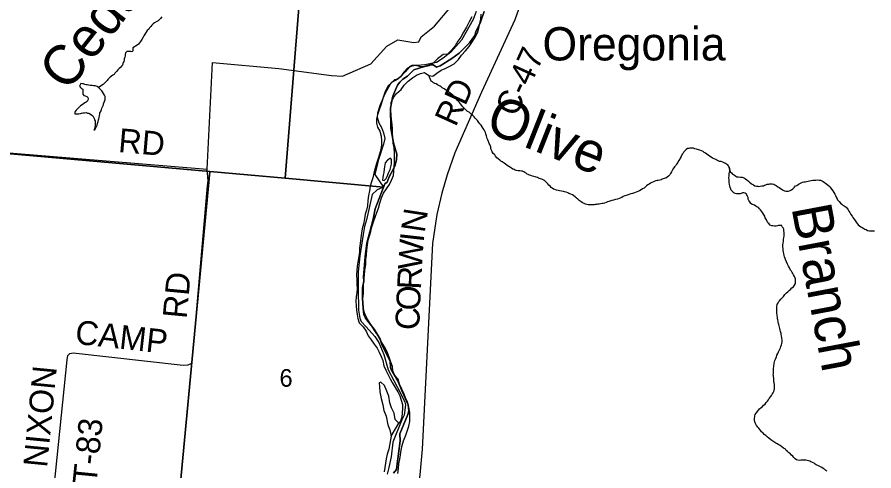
# Model space of a CAD drawing. Extents: x 1310247 to 1664935, y 284496 to 704931.
# Drawn here: x 1511194 to 1521928, y 525811 to 531499 of the extents above; entities that cross this region are included whole.
import ezdxf

# ---------------------------------------------------------------- set-up
doc = ezdxf.new("R2010")
doc.units = 0
for name, color, linetype in [('GM_X_Adjacent_County', 7, 'Continuous'), ('GM_X_City_Street', 7, 'Continuous'), ('GM_X_County', 7, 'Continuous'), ('GM_X_County_Road_Text', 7, 'Continuous'), ('GM_X_County_Subdivision_Text', 7, 'Continuous'), ('GM_X_Interstate_Route', 7, 'Continuous'), ('GM_X_Minor_Lake_Text', 7, 'Continuous'), ('GM_X_Minor_River', 7, 'Continuous'), ('GM_X_Minor_River_Text', 7, 'Continuous'), ('GM_X_Township_Road', 7, 'Continuous'), ('GM_X_Township_Subdivision', 7, 'Continuous'), ('GM_X_US_Location', 7, 'Continuous')]:
    doc.layers.add(name, color=color, linetype=linetype)

msp = doc.modelspace()

# ---------------------------------------------------------------- linework, layer by layer
at = {"layer": 'GM_X_Adjacent_County'}
for points in [[(1517045, 531569), (1517000, 531435), (1516943, 531315), (1516930, 531269), (1516862, 531178), (1516734, 531049), (1516639, 530979), (1516492, 530888), (1516449, 530870), (1516408, 530900), (1516365, 530901), (1516165, 530839), (1516086, 530759), (1516026, 530720), (1515989, 530685), (1515959, 530648), (1515909, 530527), (1515896, 530491), (1515873, 530356), (1515878, 530109), (1515911, 529925), (1515950, 529780), (1515948, 529716), (1515930, 529643), (1515910, 529596), (1515855, 529498), (1515829, 529432), (1515800, 529411), (1515679, 529094), (1515654, 528965), (1515574, 528667), (1515556, 528493), (1515532, 528243), (1515539, 528189), (1515523, 528105), (1515520, 527971), (1515534, 527805), (1515539, 527773), (1515560, 527727), (1515668, 527586), (1515742, 527463), (1515768, 527384), (1515866, 527186), (1515871, 527109), (1515881, 527082), (1515963, 526940), (1516019, 526807), (1516095, 526641), (1516103, 526562), (1516090, 526517), (1515989, 526277), (1515992, 526188), (1515953, 525866), (1515946, 525829), (1515910, 525782)], [(1515910, 525782), (1515946, 525829), (1515953, 525866), (1515992, 526188), (1515989, 526277), (1516090, 526517), (1516103, 526562), (1516095, 526641), (1516019, 526807), (1515963, 526940), (1515881, 527082), (1515871, 527109), (1515866, 527186), (1515768, 527384), (1515742, 527463), (1515668, 527586), (1515560, 527727), (1515539, 527773), (1515534, 527805), (1515520, 527971), (1515523, 528105), (1515539, 528189), (1515532, 528243), (1515556, 528493), (1515574, 528667), (1515654, 528965), (1515679, 529094), (1515800, 529411), (1515829, 529432), (1515855, 529498), (1515910, 529596), (1515930, 529643), (1515948, 529716), (1515950, 529780), (1515911, 529925), (1515878, 530109), (1515873, 530356), (1515896, 530491), (1515909, 530527), (1515959, 530648), (1515989, 530685), (1516026, 530720), (1516086, 530759), (1516165, 530839), (1516365, 530901), (1516408, 530900), (1516449, 530870), (1516492, 530888), (1516639, 530979), (1516734, 531049), (1516862, 531178), (1516930, 531269), (1516943, 531315), (1517000, 531435), (1517045, 531569)]]:
    msp.add_lwpolyline(points, dxfattribs=at)
at = {"layer": 'GM_X_City_Street'}
msp.add_line((1515881, 526248), (1515978, 526408), dxfattribs=at)
for points in [[(1515538, 528202), (1515547, 528266), (1515552, 528326), (1515561, 528398), (1515564, 528462), (1515569, 528516), (1515574, 528580), (1515583, 528646), (1515594, 528704), (1515609, 528756), (1515624, 528810), (1515639, 528869), (1515660, 528931), (1515681, 528991), (1515702, 529051), (1515721, 529105), (1515740, 529168), (1515759, 529232), (1515784, 529292), (1515820, 529345), (1515859, 529399), (1515884, 529457), (1515909, 529512), (1515914, 529566), (1515919, 529622), (1515922, 529682), (1515921, 529738), (1515922, 529792), (1515917, 529863), (1515907, 529921), (1515900, 529985), (1515897, 530049), (1515896, 530103), (1515891, 530155), (1515884, 530218), (1515881, 530268), (1515876, 530332), (1515881, 530430), (1515908, 530490), (1515949, 530543), (1516004, 530590), (1516045, 530644), (1516094, 530697), (1516147, 530740), (1516197, 530772), (1516248, 530791), (1516298, 530804), (1516351, 530767), (1516403, 530760), (1516454, 530796), (1516507, 530833), (1516557, 530856), (1516616, 530883), (1516670, 530914), (1516723, 530966), (1516762, 531021), (1516811, 531078), (1516856, 531130), (1516899, 531195), (1516934, 531249), (1516961, 531300), (1516980, 531360), (1516993, 531422), (1517004, 531474), (1517009, 531536)], [(1516890, 531504), (1516859, 531438), (1516824, 531375), (1516787, 531309)], [(1516787, 531309), (1516752, 531248), (1516717, 531196), (1516680, 531141), (1516637, 531083), (1516586, 531036), (1516532, 531031), (1516495, 531001), (1516461, 530976), (1516406, 530921), (1516355, 530889), (1516301, 530876), (1516247, 530877), (1516193, 530892), (1516141, 530885), (1516086, 530859), (1516039, 530808), (1515998, 530749), (1515944, 530707), (1515893, 530684), (1515840, 530635), (1515805, 530565), (1515786, 530502), (1515769, 530450), (1515750, 530394), (1515731, 530336), (1515709, 530276), (1515696, 530225), (1515697, 530168), (1515710, 530118), (1515737, 530068), (1515756, 530007), (1515760, 529949), (1515761, 529897), (1515750, 529841), (1515735, 529783), (1515716, 529728), (1515697, 529666), (1515680, 529606), (1515663, 529542), (1515650, 529486), (1515633, 529434), (1515619, 529379), (1515610, 529323), (1515597, 529261), (1515588, 529199), (1515583, 529133), (1515570, 529081), (1515555, 529029), (1515544, 528971), (1515533, 528905), (1515518, 528845), (1515507, 528791), (1515500, 528731), (1515491, 528663), (1515484, 528601), (1515482, 528551), (1515475, 528497), (1515464, 528428), (1515453, 528376), (1515450, 528324), (1515447, 528268), (1515448, 528207), (1515449, 528151), (1515453, 528097), (1515450, 528047), (1515443, 527993), (1515438, 527939), (1515441, 527881), (1515446, 527827), (1515454, 527771), (1515461, 527720), (1515480, 527668), (1515531, 527617), (1515565, 527561), (1515594, 527504), (1515629, 527453), (1515668, 527401), (1515704, 527348), (1515731, 527298), (1515754, 527245), (1515775, 527193), (1515788, 527128), (1515812, 527072), (1515839, 527022), (1515868, 526967), (1515893, 526917), (1515931, 526858), (1515962, 526803), (1515987, 526751), (1516006, 526696), (1516021, 526644), (1516023, 526592), (1516018, 526540), (1516015, 526486), (1515998, 526434), (1515978, 526408)], [(1515870, 529729), (1515836, 529706), (1515803, 529671), (1515801, 529646), (1515794, 529596), (1515788, 529552), (1515781, 529518), (1515775, 529490), (1515770, 529456), (1515794, 529452), (1515818, 529478), (1515831, 529503)], [(1515831, 529503), (1515852, 529557), (1515868, 529589), (1515885, 529657), (1515886, 529713), (1515870, 529729)], [(1515962, 525778), (1515973, 525842), (1515978, 525898), (1515987, 525958), (1515998, 526014), (1516007, 526071), (1516020, 526131), (1516036, 526187), (1516062, 526259), (1516082, 526311), (1516101, 526370), (1516112, 526432), (1516115, 526488), (1516114, 526545), (1516103, 526609), (1516086, 526671), (1516061, 526728), (1516038, 526784), (1516014, 526837), (1515983, 526899), (1515968, 526959), (1515921, 527010), (1515900, 527065), (1515896, 527119), (1515877, 527173), (1515856, 527238), (1515835, 527292), (1515806, 527355), (1515769, 527413), (1515734, 527472), (1515702, 527528), (1515667, 527579), (1515632, 527634), (1515595, 527690), (1515567, 527741), (1515548, 527791), (1515529, 527856), (1515524, 527910), (1515525, 527966), (1515534, 528040), (1515535, 528092), (1515534, 528148), (1515538, 528202)], [(1515978, 526408), (1515932, 526457), (1515918, 526534), (1515885, 526602), (1515863, 526665), (1515849, 526749), (1515826, 526811), (1515797, 526882), (1515749, 526923), (1515731, 526913), (1515732, 526863), (1515739, 526803), (1515756, 526720), (1515775, 526640), (1515790, 526570), (1515817, 526495), (1515839, 526389), (1515864, 526326), (1515881, 526248)], [(1515881, 526248), (1515850, 526082), (1515829, 526020), (1515817, 525962), (1515810, 525908), (1515801, 525854), (1515792, 525798)]]:
    msp.add_lwpolyline(points, dxfattribs=at)
at = {"layer": 'GM_X_County'}
for points in [[(1509752, 536706), (1515094, 536260), (1514552, 529479), (1513608, 529562), (1509176, 529957)], [(1509176, 529957), (1513608, 529562), (1513069, 523850), (1507676, 524403), (1508208, 530054)]]:
    msp.add_lwpolyline(points, close=True, dxfattribs=at)
for points in [[(1516944, 531569), (1516906, 531470), (1516760, 531212), (1516629, 531061), (1516532, 530983), (1516447, 530932), (1516303, 530902), (1516207, 530894), (1516139, 530891), (1516116, 530882), (1516055, 530813), (1515998, 530752), (1515964, 530722), (1515920, 530715), (1515875, 530670), (1515801, 530539), (1515742, 530398), (1515708, 530297), (1515705, 530243), (1515726, 530173), (1515761, 530114), (1515786, 530050), (1515799, 529977), (1515786, 529908), (1515720, 529715), (1515709, 529665), (1515677, 529526), (1515782, 529366), (1514552, 529479), (1515094, 536260)], [(1513069, 523850), (1513608, 529562), (1514552, 529479), (1515782, 529366), (1515704, 529333), (1515641, 529274), (1515610, 529127), (1515573, 528960), (1515546, 528874), (1515528, 528775), (1515487, 528505), (1515468, 528308), (1515468, 528092), (1515470, 527826), (1515486, 527724), (1515503, 527685), (1515566, 527616), (1515674, 527496), (1515724, 527421), (1515788, 527272), (1515844, 527079), (1515914, 526944), (1516001, 526779), (1516053, 526672), (1516061, 526640), (1516045, 526508), (1516013, 526449), (1515901, 526171), (1515880, 525987), (1515849, 525852), (1515828, 525770)]]:
    msp.add_lwpolyline(points, dxfattribs=at)
at = {"layer": 'GM_X_County_Road_Text'}
msp.add_lwpolyline([(1517821, 531984), (1517731, 532060), (1517631, 532163), (1517557, 531889), (1517498, 531653), (1517430, 531466), (1517014, 530559), (1516676, 529797), (1516581, 529524), (1516514, 529294), (1516453, 529026), (1516398, 528660), (1516269, 526085), (1516241, 525763), (1516213, 525605), (1516112, 525362), (1515971, 525133), (1515662, 524760)], dxfattribs=at)
at = {"layer": 'GM_X_County_Subdivision_Text'}
for points in [[(1513575, 529592), (1513641, 530929), (1514474, 530857), (1515134, 530767), (1515270, 530757), (1515627, 530915), (1515826, 531133), (1515963, 531215), (1516163, 531181), (1516227, 531188), (1516254, 531250), (1516421, 531386), (1516627, 531628), (1516762, 531921), (1516806, 532231), (1516709, 532812), (1516715, 532994)], [(1508204, 530036), (1513575, 529592)], [(1513581, 529384), (1513586, 529448), (1513575, 529592)], [(1511247, 524193), (1511369, 525485), (1511390, 525537), (1511442, 525545), (1511595, 525529), (1511640, 525529), (1511659, 525612), (1511821, 527204), (1511830, 527256), (1511854, 527283), (1511897, 527290), (1513276, 527136), (1513336, 527141), (1513384, 527163), (1513389, 527215), (1513581, 529384)]]:
    msp.add_lwpolyline(points, dxfattribs=at)
at = {"layer": 'GM_X_Minor_River'}
for points in [[(1511993, 530668), (1511974, 530633), (1511988, 530618), (1512002, 530606), (1512016, 530594), (1512019, 530580), (1512017, 530559), (1512016, 530533), (1512030, 530515), (1512048, 530511), (1512066, 530502), (1512080, 530490), (1512085, 530474), (1512081, 530460), (1512073, 530442), (1512058, 530432), (1512044, 530424), (1512026, 530413), (1512007, 530401), (1511989, 530385), (1511968, 530367), (1511950, 530350), (1511933, 530334), (1511923, 530316), (1511916, 530302), (1511918, 530286), (1511932, 530286), (1511954, 530285), (1511968, 530287), (1511987, 530291), (1512001, 530295), (1512019, 530298), (1512039, 530300), (1512059, 530302), (1512077, 530297), (1512091, 530293), (1512111, 530284), (1512129, 530272), (1512143, 530260), (1512151, 530244), (1512158, 530227), (1512164, 530213), (1512170, 530199), (1512172, 530185), (1512171, 530171), (1512173, 530141), (1512168, 530123), (1512162, 530099), (1512155, 530083), (1512172, 530094), (1512180, 530110), (1512190, 530126), (1512195, 530144), (1512201, 530166), (1512208, 530192), (1512212, 530210), (1512217, 530226), (1512221, 530242), (1512224, 530266), (1512228, 530284), (1512230, 530298), (1512241, 530316), (1512250, 530342), (1512254, 530358), (1512262, 530376), (1512275, 530400), (1512277, 530414), (1512286, 530432), (1512292, 530452), (1512297, 530466), (1512297, 530480), (1512295, 530502), (1512288, 530522), (1512276, 530543), (1512264, 530561), (1512253, 530577), (1512213, 530618)], [(1512213, 530618), (1512198, 530628), (1512184, 530633), (1512170, 530637), (1512151, 530639), (1512135, 530640), (1512121, 530640), (1512107, 530640), (1512089, 530645), (1512073, 530649), (1512059, 530651), (1512043, 530655), (1512027, 530662), (1512011, 530664), (1511993, 530668)]]:
    msp.add_lwpolyline(points, dxfattribs=at)
at = {"layer": 'GM_X_Minor_River_Text'}
for points in [[(1513006, 531504), (1512990, 531482), (1512975, 531466), (1512959, 531454), (1512943, 531445), (1512914, 531427), (1512900, 531415), (1512883, 531397), (1512871, 531382), (1512852, 531366), (1512842, 531350), (1512825, 531330), (1512802, 531296), (1512788, 531279), (1512780, 531265), (1512771, 531247), (1512756, 531219), (1512738, 531195), (1512727, 531177), (1512715, 531161), (1512698, 531146), (1512678, 531134), (1512664, 531126), (1512645, 531115), (1512643, 531092), (1512644, 531078), (1512632, 531065), (1512618, 531067), (1512600, 531067), (1512586, 531067), (1512570, 531066), (1512553, 531050), (1512549, 531030), (1512546, 531012), (1512544, 530998), (1512536, 530978), (1512533, 530960), (1512529, 530944), (1512524, 530930), (1512520, 530916), (1512512, 530898), (1512501, 530884), (1512487, 530868), (1512472, 530854), (1512456, 530837), (1512441, 530823), (1512431, 530809), (1512417, 530795), (1512408, 530781), (1512392, 530772), (1512376, 530758), (1512361, 530746), (1512349, 530732), (1512332, 530718), (1512320, 530705), (1512304, 530689), (1512287, 530673), (1512271, 530655), (1512213, 530618)], [(1516857, 530306), (1516837, 530318), (1516821, 530331), (1516807, 530347), (1516793, 530357), (1516778, 530376), (1516766, 530390), (1516748, 530412), (1516735, 530429), (1516721, 530445), (1516707, 530459), (1516690, 530482), (1516680, 530496), (1516666, 530504), (1516652, 530521), (1516636, 530535), (1516621, 530547), (1516603, 530560), (1516587, 530570), (1516573, 530578), (1516559, 530589), (1516543, 530599), (1516521, 530614), (1516507, 530624), (1516494, 530632), (1516478, 530642), (1516460, 530651), (1516442, 530661), (1516428, 530669), (1516412, 530676), (1516396, 530688), (1516382, 530698), (1516351, 530767)], [(1518331, 529150), (1518317, 529154), (1518297, 529162), (1518277, 529173), (1518259, 529185), (1518237, 529202), (1518219, 529216), (1518200, 529235), (1518186, 529247), (1518168, 529259), (1518150, 529270), (1518130, 529280), (1518108, 529290), (1518094, 529297), (1518072, 529305), (1518052, 529310), (1518038, 529314), (1518014, 529318), (1517990, 529323), (1517974, 529325), (1517950, 529330), (1517930, 529338), (1517914, 529344), (1517898, 529353), (1517884, 529363), (1517871, 529379), (1517857, 529392), (1517841, 529410), (1517827, 529426), (1517814, 529439), (1517800, 529449), (1517786, 529461), (1517768, 529468), (1517750, 529474), (1517728, 529482), (1517712, 529489), (1517698, 529493), (1517684, 529495), (1517668, 529501), (1517650, 529506), (1517632, 529512), (1517614, 529519), (1517598, 529525), (1517584, 529531), (1517570, 529541), (1517554, 529552), (1517541, 529560), (1517527, 529566), (1517511, 529569), (1517494, 529571), (1517470, 529573), (1517448, 529578), (1517434, 529582), (1517420, 529588), (1517404, 529595), (1517389, 529607), (1517375, 529613), (1517355, 529626), (1517333, 529640), (1517313, 529655), (1517297, 529667), (1517283, 529675), (1517270, 529686), (1517256, 529694), (1517240, 529706), (1517222, 529721), (1517206, 529735), (1517187, 529755), (1517177, 529772), (1517159, 529788), (1517146, 529810), (1517140, 529825), (1517134, 529839), (1517130, 529853), (1517129, 529867), (1517123, 529883), (1517115, 529901), (1517110, 529916), (1517098, 529938), (1517091, 529960), (1517083, 529978), (1517079, 529995), (1517076, 530009), (1517070, 530023), (1517066, 530037), (1517060, 530051), (1517055, 530069), (1517045, 530086), (1517033, 530104), (1517020, 530124), (1517006, 530145), (1516990, 530163), (1516977, 530179), (1516961, 530204), (1516947, 530218), (1516934, 530234), (1516920, 530251), (1516904, 530267), (1516888, 530279), (1516870, 530294), (1516857, 530306)], [(1520035, 529679), (1520014, 529688), (1519995, 529690), (1519979, 529696), (1519960, 529707), (1519946, 529713), (1519926, 529723), (1519908, 529732), (1519888, 529744), (1519870, 529756), (1519850, 529769), (1519834, 529783), (1519819, 529794), (1519803, 529804), (1519789, 529814), (1519767, 529825), (1519749, 529833), (1519729, 529837), (1519707, 529844), (1519685, 529850), (1519667, 529855), (1519651, 529855), (1519637, 529855), (1519623, 529855), (1519609, 529854), (1519594, 529852), (1519576, 529840), (1519560, 529822), (1519547, 529809), (1519539, 529795), (1519528, 529781), (1519512, 529751), (1519503, 529731), (1519495, 529717), (1519482, 529697), (1519470, 529677), (1519455, 529656), (1519445, 529638), (1519432, 529624), (1519422, 529610), (1519411, 529592), (1519401, 529578), (1519393, 529560), (1519380, 529540), (1519370, 529521), (1519353, 529505), (1519339, 529493), (1519320, 529481), (1519302, 529476), (1519276, 529466), (1519262, 529460), (1519245, 529457), (1519227, 529453), (1519213, 529449), (1519197, 529445), (1519183, 529442), (1519168, 529436), (1519148, 529426), (1519130, 529416), (1519111, 529407), (1519095, 529395), (1519081, 529385), (1519066, 529373), (1519048, 529356), (1519029, 529346), (1519011, 529334), (1518991, 529323), (1518970, 529313), (1518950, 529303), (1518930, 529298), (1518903, 529288), (1518883, 529282), (1518869, 529279), (1518851, 529271), (1518826, 529263), (1518806, 529258), (1518788, 529250), (1518769, 529238), (1518735, 529225), (1518715, 529219), (1518690, 529212), (1518666, 529206), (1518646, 529200), (1518632, 529197), (1518607, 529189), (1518589, 529183), (1518575, 529175), (1518554, 529168), (1518536, 529164), (1518522, 529162), (1518504, 529159), (1518488, 529155), (1518470, 529153), (1518455, 529152), (1518437, 529150), (1518423, 529148), (1518401, 529146), (1518383, 529147), (1518363, 529147), (1518347, 529147), (1518331, 529150)], [(1520947, 528200), (1520945, 528214), (1520941, 528228), (1520933, 528248), (1520922, 528270), (1520914, 528285), (1520904, 528299), (1520895, 528315), (1520885, 528329), (1520869, 528356), (1520858, 528378), (1520844, 528404), (1520833, 528433), (1520821, 528461), (1520816, 528475), (1520810, 528494), (1520806, 528510), (1520801, 528536), (1520795, 528554), (1520792, 528574), (1520790, 528598), (1520789, 528621), (1520789, 528643), (1520792, 528667), (1520794, 528689), (1520797, 528703), (1520797, 528717), (1520799, 528731), (1520802, 528757), (1520803, 528783), (1520803, 528797), (1520799, 528825), (1520798, 528839), (1520790, 528856), (1520780, 528872), (1520773, 528886), (1520753, 528888), (1520734, 528887), (1520720, 528883), (1520704, 528879), (1520684, 528880), (1520664, 528882), (1520650, 528884), (1520630, 528893), (1520612, 528911), (1520598, 528921), (1520591, 528938), (1520581, 528960), (1520567, 528982), (1520562, 529004), (1520546, 529029), (1520531, 529051), (1520521, 529067), (1520507, 529084), (1520493, 529096), (1520482, 529114), (1520462, 529123), (1520448, 529131), (1520434, 529141), (1520418, 529148), (1520404, 529152), (1520388, 529164), (1520373, 529183), (1520363, 529201), (1520355, 529219), (1520352, 529237), (1520346, 529256), (1520329, 529284), (1520315, 529292), (1520299, 529295), (1520281, 529295), (1520266, 529289), (1520252, 529285), (1520232, 529282), (1520208, 529284), (1520192, 529288), (1520174, 529297), (1520160, 529307), (1520142, 529330), (1520137, 529344), (1520129, 529364), (1520124, 529386), (1520120, 529400), (1520114, 529427), (1520113, 529441), (1520113, 529459), (1520112, 529485), (1520114, 529509), (1520115, 529523), (1520117, 529537), (1520119, 529555), (1520122, 529571), (1520122, 529585), (1520120, 529599), (1520113, 529619), (1520107, 529634), (1520097, 529648), (1520083, 529656), (1520069, 529666), (1520051, 529673), (1520035, 529679)], [(1520113, 529619), (1520129, 529559), (1520145, 529547), (1520155, 529532), (1520169, 529528), (1520183, 529516), (1520197, 529505), (1520213, 529499), (1520233, 529495), (1520255, 529492), (1520277, 529492), (1520291, 529490), (1520305, 529481), (1520319, 529473), (1520337, 529459), (1520356, 529444), (1520370, 529430), (1520390, 529415), (1520404, 529405), (1520418, 529397), (1520438, 529386), (1520456, 529380), (1520474, 529378), (1520488, 529377), (1520502, 529379), (1520524, 529383), (1520544, 529386), (1520558, 529392), (1520573, 529398), (1520593, 529404), (1520611, 529407), (1520625, 529411), (1520639, 529411), (1520654, 529411), (1520674, 529406), (1520687, 529398), (1520703, 529390), (1520723, 529373), (1520741, 529363), (1520759, 529350), (1520777, 529338), (1520793, 529330), (1520809, 529323), (1520827, 529317), (1520841, 529317), (1520859, 529318), (1520881, 529326), (1520895, 529336), (1520912, 529348), (1520932, 529367), (1520945, 529383), (1520961, 529387), (1520979, 529399), (1520994, 529408), (1521008, 529418), (1521034, 529430), (1521049, 529434), (1521069, 529435), (1521085, 529437), (1521105, 529441), (1521121, 529446), (1521142, 529450), (1521164, 529454), (1521184, 529455), (1521202, 529457), (1521222, 529458), (1521242, 529456), (1521258, 529454), (1521276, 529445), (1521292, 529437), (1521310, 529427), (1521324, 529416), (1521340, 529406), (1521364, 529386), (1521377, 529371), (1521389, 529357), (1521397, 529341), (1521415, 529322), (1521426, 529300), (1521438, 529280), (1521449, 529261), (1521457, 529243), (1521469, 529223), (1521474, 529209), (1521494, 529186), (1521510, 529168), (1521525, 529154), (1521541, 529141), (1521557, 529133), (1521579, 529116), (1521597, 529098), (1521606, 529084), (1521614, 529068), (1521628, 529051), (1521639, 529025), (1521655, 529006), (1521663, 528988), (1521676, 528970), (1521692, 528948), (1521708, 528929), (1521719, 528913)], [(1521719, 528913), (1521731, 528897), (1521749, 528884), (1521763, 528872), (1521781, 528862), (1521801, 528851), (1521814, 528841), (1521830, 528835), (1521850, 528826), (1521872, 528820), (1521892, 528819), (1521913, 528819), (1521935, 528819)], [(1520449, 526396), (1520439, 526415), (1520434, 526437), (1520432, 526455), (1520433, 526473), (1520435, 526487), (1520435, 526501), (1520442, 526517), (1520452, 526535), (1520469, 526555), (1520481, 526573), (1520494, 526588), (1520514, 526606), (1520531, 526620), (1520545, 526634), (1520564, 526649), (1520578, 526667), (1520594, 526683), (1520609, 526703), (1520617, 526719), (1520636, 526745), (1520646, 526758), (1520655, 526772), (1520665, 526790), (1520674, 526808), (1520678, 526822), (1520682, 526836), (1520685, 526850), (1520685, 526864), (1520683, 526882), (1520682, 526896), (1520680, 526913), (1520676, 526929), (1520675, 526945), (1520673, 526963), (1520670, 527001), (1520668, 527017), (1520669, 527033), (1520669, 527049), (1520670, 527074), (1520672, 527096), (1520675, 527120), (1520675, 527134), (1520677, 527148), (1520680, 527162), (1520682, 527178), (1520688, 527196), (1520695, 527212), (1520706, 527240), (1520714, 527260), (1520725, 527281), (1520735, 527303), (1520750, 527337), (1520758, 527353), (1520763, 527369), (1520771, 527391), (1520774, 527409), (1520780, 527429), (1520779, 527447), (1520775, 527477), (1520770, 527506), (1520766, 527520), (1520767, 527534), (1520757, 527560), (1520753, 527576), (1520748, 527594), (1520744, 527611), (1520740, 527629), (1520737, 527645), (1520733, 527659), (1520729, 527675), (1520728, 527689), (1520724, 527703), (1520722, 527718), (1520719, 527740), (1520717, 527754), (1520717, 527768), (1520714, 527782), (1520714, 527796), (1520712, 527816), (1520713, 527832), (1520713, 527850), (1520714, 527870), (1520716, 527896), (1520723, 527910), (1520733, 527930), (1520746, 527944), (1520762, 527964), (1520776, 527978), (1520795, 527998), (1520814, 528021), (1520834, 528041), (1520849, 528057), (1520869, 528075), (1520884, 528086), (1520902, 528104), (1520919, 528120), (1520933, 528138), (1520944, 528160), (1520948, 528178), (1520947, 528200)], [(1521340, 525807), (1521326, 525818), (1521308, 525832), (1521292, 525842), (1521276, 525853), (1521259, 525863), (1521241, 525872), (1521227, 525878), (1521207, 525886), (1521193, 525897), (1521179, 525907), (1521159, 525915), (1521139, 525924), (1521125, 525932), (1521107, 525938), (1521091, 525943), (1521075, 525945), (1521061, 525947), (1521045, 525947), (1521031, 525946), (1521013, 525944), (1520993, 525942), (1520975, 525945), (1520959, 525951), (1520941, 525963), (1520927, 525980), (1520913, 525994), (1520897, 526010), (1520874, 526033), (1520860, 526041), (1520844, 526056), (1520830, 526066), (1520819, 526082), (1520795, 526097), (1520773, 526113), (1520753, 526128), (1520737, 526138), (1520715, 526150), (1520701, 526157), (1520688, 526167), (1520674, 526175), (1520650, 526194), (1520636, 526202), (1520612, 526223), (1520591, 526237), (1520573, 526253), (1520555, 526268), (1520539, 526282), (1520521, 526299), (1520510, 526313), (1520500, 526331), (1520486, 526345), (1520475, 526360), (1520459, 526382), (1520449, 526396)]]:
    msp.add_lwpolyline(points, dxfattribs=at)

# ---------------------------------------------------------------- texts
at = {"layer": 'GM_X_Interstate_Route'}
msp.add_text('Oregonia', height=417, rotation=0, dxfattribs=at).set_placement((1517776, 530956))
at = {"layer": 'GM_X_Minor_Lake_Text'}
for s, height, rotation, p in [('Cedar', 500, 51.8791, (1511826, 530550)), ('Olive', 500, 338.4228, (1517041, 530072)), ('Branch', 500.1, 280.7121, (1520894, 529111))]:
    msp.add_text(s, height=height, rotation=rotation, dxfattribs=at).set_placement(p)
at = {"layer": 'GM_X_Township_Road'}
for s, rotation, p in [('C-47', 65.5735, (1517446, 530237)), ('RD', 65.6372, (1516688, 530113)), ('N', 81.3485, (1516299, 528788)), ('I', 83.7115, (1516286, 528669)), ('W', 86.5534, (1516265, 528326)), ('R', 87.2395, (1516253, 528080)), ('O', 87.2434, (1516240, 527817)), ('C', 87.2395, (1516229, 527571))]:
    msp.add_text(s, height=300, rotation=rotation, dxfattribs=at).set_placement(p)
at = {"layer": 'GM_X_Township_Subdivision'}
for s, rotation, p in [('RD', 355.0719, (1512454, 529808)), ('RD', 84.5841, (1513316, 527712)), ('CAMP', 353.7129, (1511911, 527405)), ('NIXON', 84.4388, (1511569, 525847)), ('T-83', 84.325, (1512187, 525635))]:
    msp.add_text(s, height=300, rotation=rotation, dxfattribs=at).set_placement(p)
at = {"layer": 'GM_X_US_Location'}
msp.add_text('6', height=221, rotation=0, dxfattribs=at).set_placement((1514481, 526866))

doc.saveas('drawing.dxf')
